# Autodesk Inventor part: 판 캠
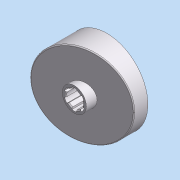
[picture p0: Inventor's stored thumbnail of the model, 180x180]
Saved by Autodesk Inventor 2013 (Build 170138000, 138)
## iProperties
Company: 한국ATC센터
Created: 2014-07
Part Number: 판 캠
Document SubType Name: 모델링
Designer: KYOUNG IL JANG
Material: 강철
Density: 1 g/cm^3
변환 표준: STEP AP214IS
파일 이름: C:\Users\SeoGD\Desktop\?쒗뿕\??stp
전처리기: Build: 253, Release: 2010 SP1 - Date: Wed 07/29/2009
전송 단위: 밀리미터
불확실성: 0.01
Author: KYOUNG IL JANG
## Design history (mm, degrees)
node "작업 평면4"
sketch "스케치1"
  geometry: C1 r 44.5 at (0, 0); 1 further point
  constraints: 1 centre point, 1 coincident
  dimensions: "d25" = 89 diameter of C1
extrude "돌출1" new body sketch "스케치1" distance "d1" = 40; taper "d2" = 0 deg
sketch "스케치2"
  geometry: L1 (-44.5, 15)-(44.5, 38.847); L2 (-44.5, 0)-(-44.5, 40) reference; L3 (-44.5, 40)-(44.5, 40) reference; L4 (44.5, 0)-(44.5, 40) reference; 1 further point
  constraints: 2 end point, 2 point on line
  dimensions: "d26" = 15 distance of L2.start L1.start; "d27" = 75 deg angle of L1 L2
extrude "돌출2" cut sketch "스케치2" stored distance "d5" = 40; taper "d6" = 0 deg
node "작업 평면1"
sketch "스케치3"
  geometry: C1 r 13 at (0, 0); 1 further point
  constraints: 1 centre point, 1 coincident
  dimensions: "d9" = 26 diameter of C1
extrude "돌출3" join sketch "스케치3" distance "d10" = 38; taper "d11" = 0 deg
hole "구멍1" diameter "d14" = 18; stored, may be unused: countersink angle "d18" = 90 deg, drill point angle "d20" = 118 deg; dims "d12" = 10, "d13" = 10, "d15" = 6, "d16" = 4, "d17" = 2, "d19" = 8
feature "쉘2" dims "d29" = 5
sketch "스케치6"
  geometry: C1 r 17.5 at (0, 0); C2 r 14 at (0, 0) reference; 1 further point
  constraints: 1 centre point, 1 coincident
  dimensions: "d28" = 35 diameter of C1
extrude "돌출4" join sketch "스케치6" stored distance "d30" = 38; taper "d31" = 0 deg
fillet "모깎기1" dims "d32" = 3
chamfer "모따기1" distance "d21" = 1; stored, may be unused: second distance "d22" = 2, angle "d23" = 45 deg
sketch "스케치7"
  geometry: L1 (-12.374, 12.374)-(-27.931, 27.931); A1 r 39.5 centre (0, 0) between (-27.931, 27.931) and (0, 39.5) reference; 2 further points
  constraints: 2 end point, 2 point on circle, 1 point on line, 1 vertical alignment, 2 other
  dimensions: "d33" = 45 deg dimension on point (0, 0) L1.start A1.end
feature "리브1" sketch "스케치7" dims "d34" = 5, "d35" = 1, "d36" = 0
fillet "모깎기2" dims "d37" = 3
sketch "스케치8"
  geometry: L1 (2.5, 10.712)-(2.5, 8.646); L2 (-2.5, 10.712)-(-2.5, 8.646); A1 r 11 centre (0, 0) between (2.5, 10.712) and (-2.5, 10.712); A2 r 9 centre (0, 0) between (2.5, 8.646) and (-2.5, 8.646) reference; 1 further point
  constraints: 4 end point, 4 point on circle, 2 parallel, 1 centre point, 1 coincident, 1 vertical
  dimensions: "d41" = 22 diameter of A1; "d42" = 5 distance between parallel lines of L1 L2
extrude "돌출5" cut sketch "스케치8" stored distance "d43" = 38; taper "d44" = 0 deg
fillet "모깎기3" dims "d48" = 1
node "솔리드1"
node "솔리드 본체"
node "곡면 본체"
pattern_circular "원형 패턴1" dims angle "d39" = 360 deg
pattern_circular "원형 패턴2" dims angle "d46" = 360 deg
node "솔리드2"
